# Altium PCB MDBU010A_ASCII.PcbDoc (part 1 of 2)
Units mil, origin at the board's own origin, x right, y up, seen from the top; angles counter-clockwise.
Board outline 3300 x 2500 mil, 2 copper layers (Top Layer, Bottom Layer), stack 64.8 mil thick; 105 components, 70 nets, 307 pads, 460 vias.
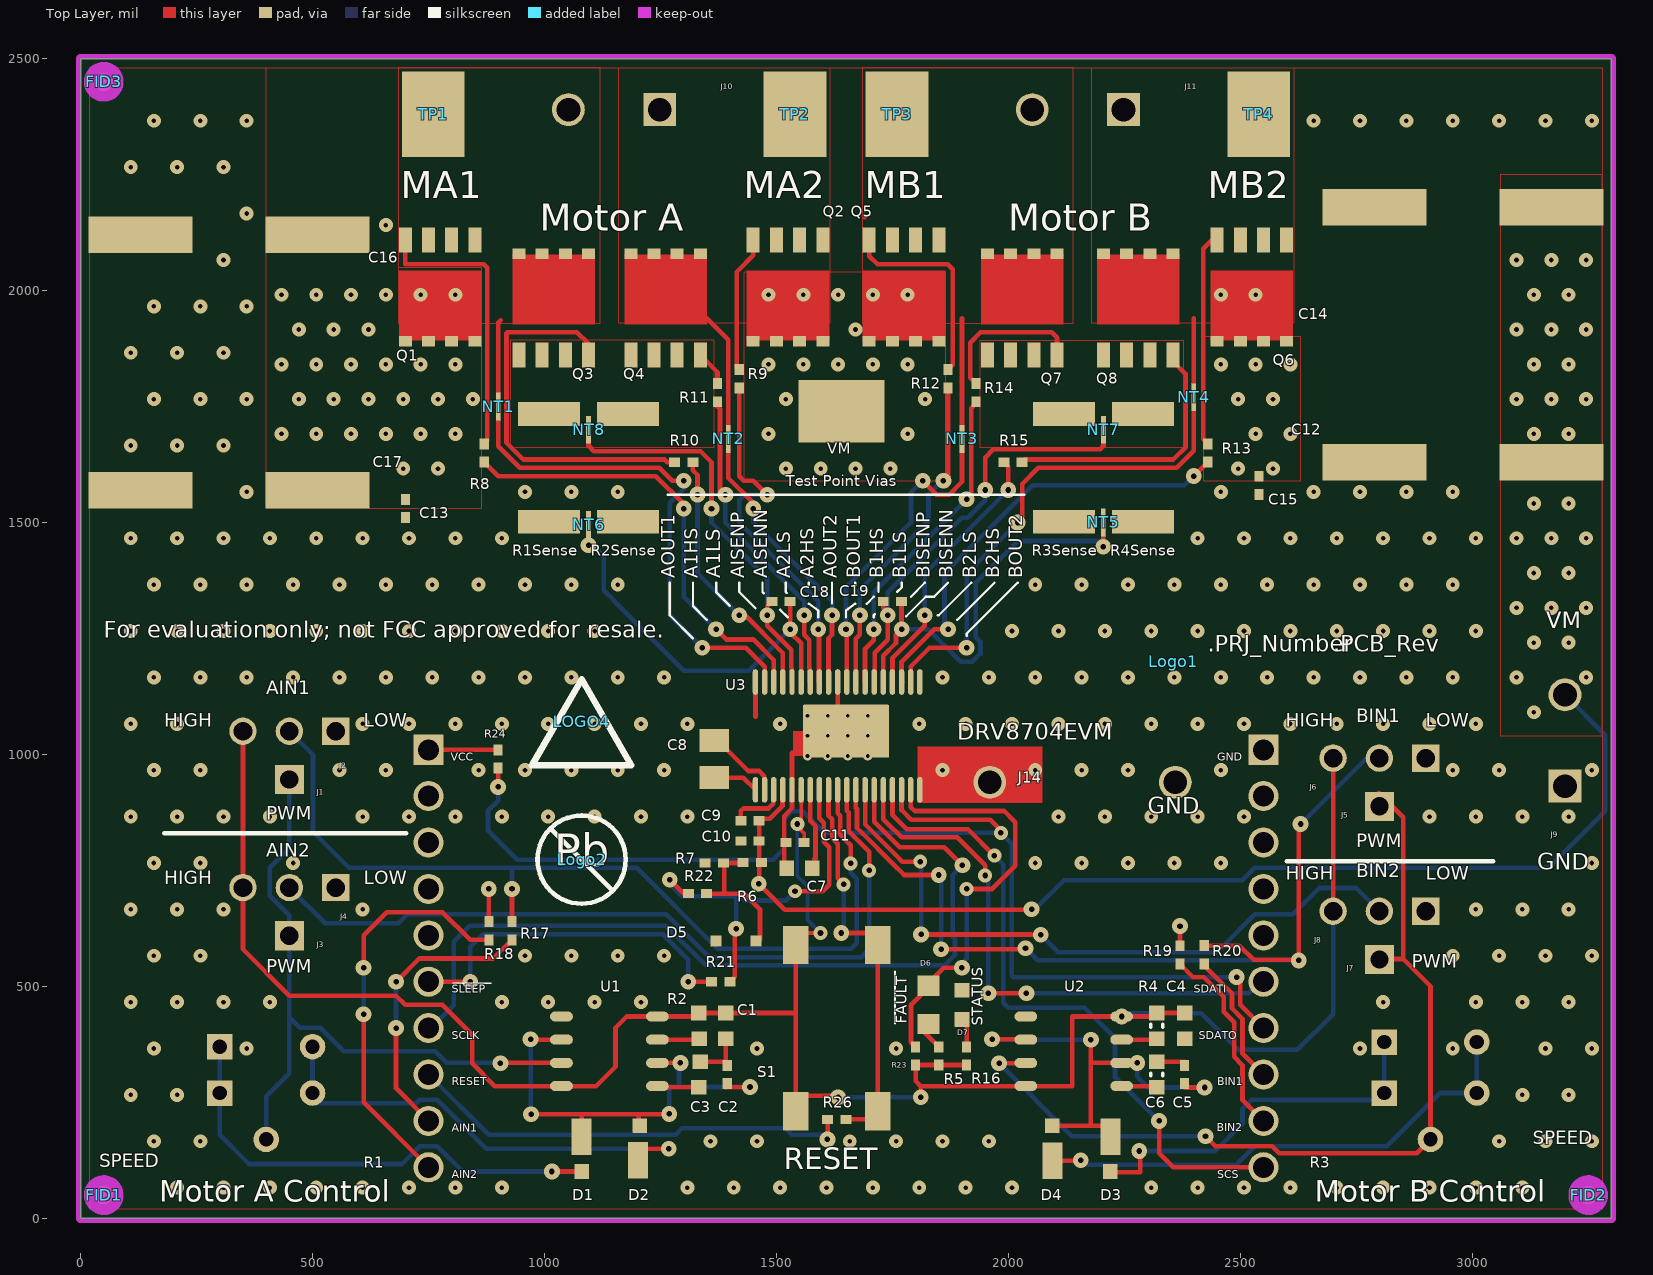
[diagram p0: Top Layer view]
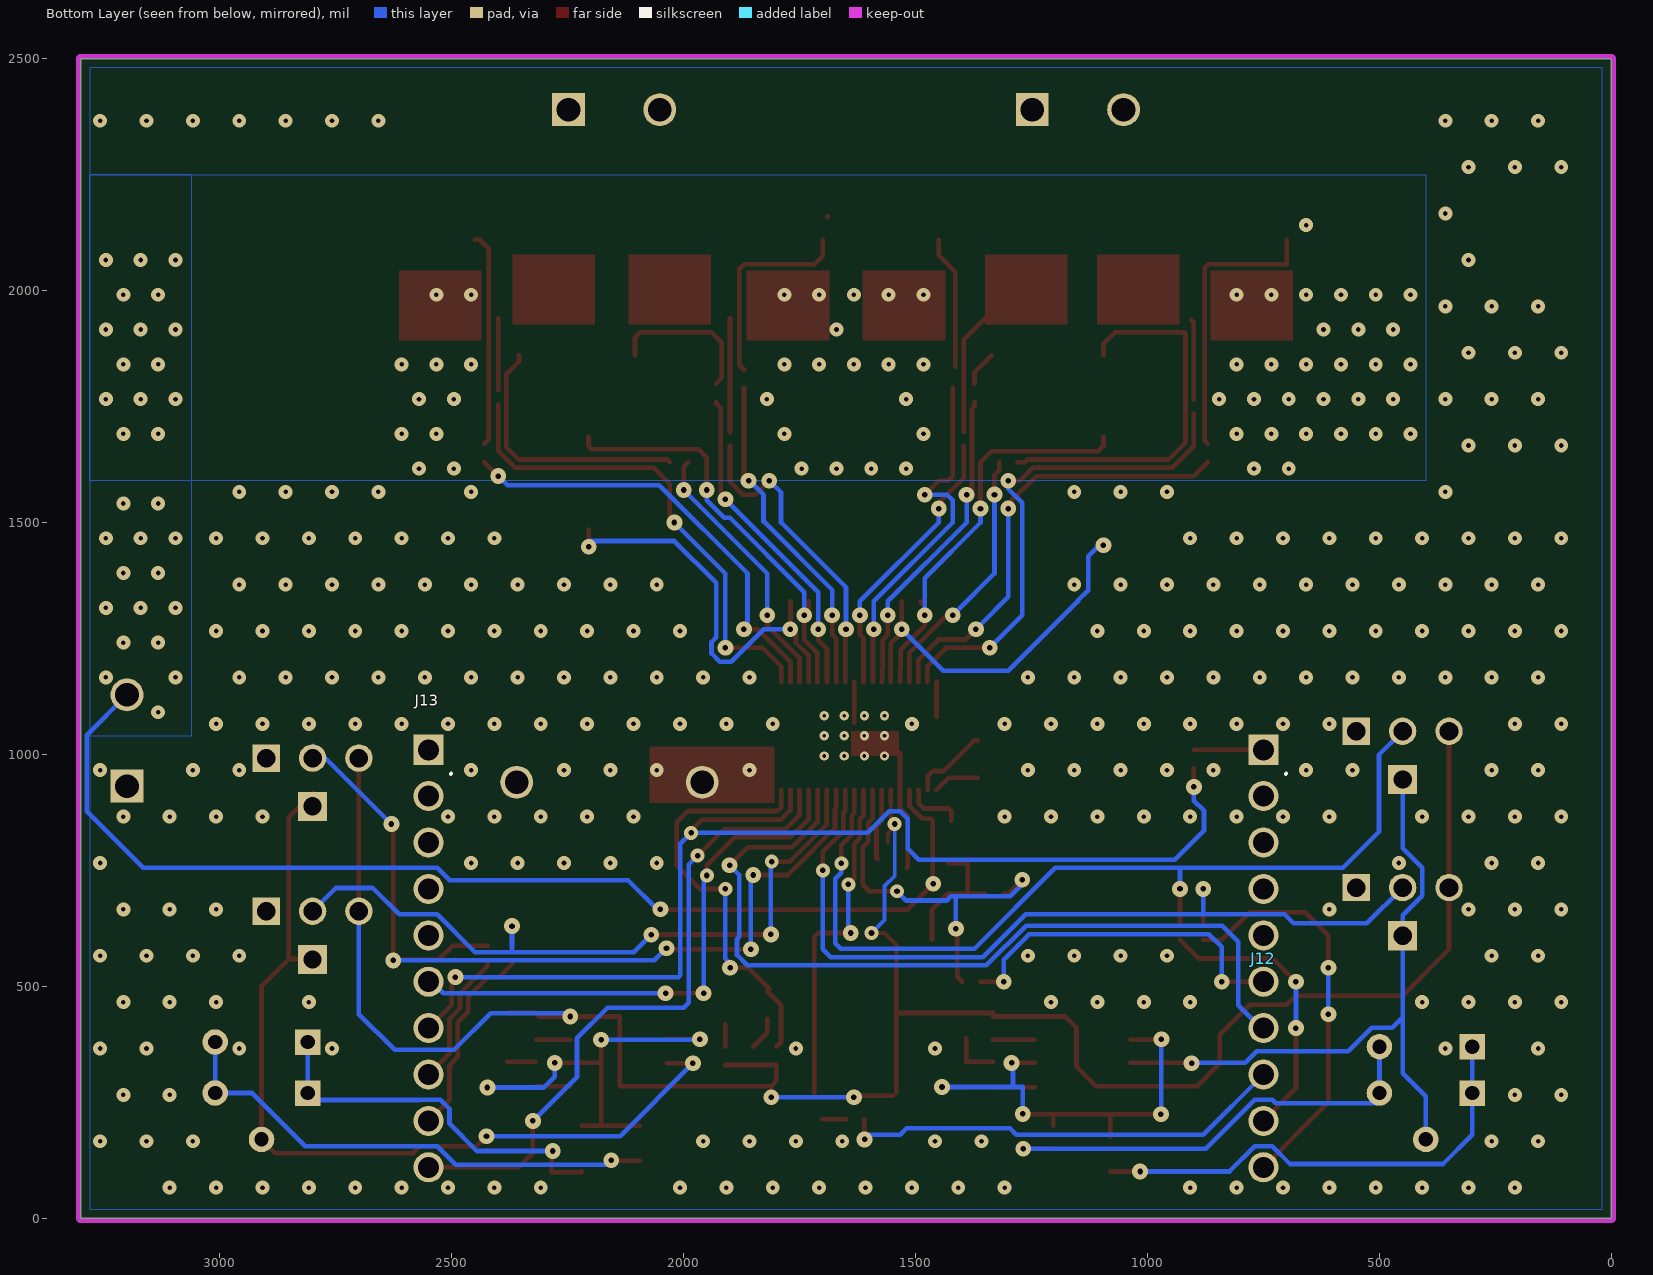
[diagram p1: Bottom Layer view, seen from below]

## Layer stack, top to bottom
Top Solder: solder mask 0.4, Solder Resist, Dk 3.5
Top Layer: signal copper 2.8
Dielectric1: core 59.2, FR-4, Dk 4.8
Bottom Layer: signal copper 2.8
Bottom Solder: solder mask 0.4, Solder Resist, Dk 3.5

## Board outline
0,0 3300,0 3300,2500 0,2500

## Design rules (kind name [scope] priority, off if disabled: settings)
AcuteAngle [All] p0: scope1count=1 scope1_0_kind=Board scope1_0_value=Board scope2count=1 scope2_0_kind=Board scope2_0_value=Board commentlength=0 minimum=4.50000000000000E+0001
AcuteAngle [All] p1: minimum=4.50000000000000E+0001 checktracksonly=FALSE
AssemblyTestPointUsage [All] p0: scope1count=1 scope1_0_kind=Board scope1_0_value=Board scope2count=1 scope2_0_kind=Board scope2_0_value=Board commentlength=0
AssemblyTestPointUsage [All] p1: valid=2
AssemblyTestpoint [All] p0: scope1count=1 scope1_0_kind=Board scope1_0_value=Board scope2count=1 scope2_0_kind=Board scope2_0_value=Board commentlength=0
Clearance Clearance_2 [All] p0: scope1count=1 scope1_0_kind=Board scope1_0_value=Board scope2count=1 scope2_0_kind=Board scope2_0_value=Board commentlength=0 gap=10
Clearance Clearance_1 [All] p0: scope1count=1 scope1_0_kind=Board scope1_0_value=Board scope2count=1 scope2_0_kind=Board scope2_0_value=Board commentlength=0 gap=10
Clearance [All] p0: scope1count=1 scope1_0_kind=Board scope1_0_value=Board scope2count=1 scope2_0_kind=Board scope2_0_value=Board commentlength=0 gap=7.87
Clearance Clearance_Poly [All] p0 off: scope1count=1 scope1_0_kind=Board scope1_0_value=Board scope2count=1 scope2_0_kind=Board scope2_0_value=Board commentlength=48 gap=25 // Protel DXP Scope 1 Expression Was: InPolygon
Clearance Clearance_BoardEdge [All] p0 off: scope1count=1 scope1_0_kind=Board scope1_0_value=Board scope2count=1 scope2_0_kind=Board scope2_0_value=Board commentlength=48 gap=75 // Protel DXP Scope 2 Expression Was: IsKeepOut
Clearance Clearance_BoardEdge_Poly [All] p0 off: scope1count=1 scope1_0_kind=Board scope1_0_value=Board scope2count=1 scope2_0_kind=Board scope2_0_value=Board commentlength=48 gap=25 // Protel DXP Scope 2 Expression Was: IsKeepOut
Clearance Clearance_BoardEdge_MountingHoles [All] p0 off: scope1count=1 scope1_0_kind=Board scope1_0_value=Board scope2count=1 scope2_0_kind=Board scope2_0_value=Board commentlength=48 gap=40 // Protel DXP Scope 2 Expression Was: IsKeepOut
Clearance Clearance_Keepouts [All] p0 off: scope1count=1 scope1_0_kind=Board scope1_0_value=Board scope2count=1 scope2_0_kind=Board scope2_0_value=Board commentlength=99 gap=0 // Protel DXP Scope 2 Expression Was: ((IsTrack Or IsArc) And Not InPoly) And IsFree and IsKeepOut
Clearance [All] p1: gap=7.87 ignorepadtopadclearanceinfootprint=FALSE except(0: Arc-Hole Track-Hole SMDPad-Hole THPad-Hole Via-Hole Fill-Hole Poly-Hole Region-Hole Text-Hole)
Clearance Clearance_2 [All] p2: gap=10 ignorepadtopadclearanceinfootprint=FALSE except(0: Arc-Hole Track-Hole SMDPad-Hole THPad-Hole Via-Hole Fill-Hole Poly-Hole Region-Hole Text-Hole)
Clearance Clearance_1 [All] p3: gap=10 ignorepadtopadclearanceinfootprint=FALSE except(0: Arc-Hole Track-Hole SMDPad-Hole THPad-Hole Via-Hole Fill-Hole Poly-Hole Region-Hole Text-Hole)
Clearance Clearance_Keepouts [((IsTrack Or IsArc) And Not InPoly) And IsFree and IsKeepOut vs ((IsTrack Or IsArc) And Not InPoly) And IsFree and IsKeepOut] p4: gap=0 ignorepadtopadclearanceinfootprint=FALSE
Clearance Clearance_BoardEdge_MountingHoles [OnCopper and InComponentClass('Mounting Holes') vs IsKeepOut] p5: gap=40 ignorepadtopadclearanceinfootprint=FALSE except(0: Arc-Hole Track-Hole SMDPad-Hole THPad-Hole Via-Hole Fill-Hole Poly-Hole Region-Hole Text-Hole)
Clearance Clearance_BoardEdge_Poly [OnCopper and InPoly vs IsKeepOut] p6: gap=25 ignorepadtopadclearanceinfootprint=FALSE except(0: Arc-Hole Track-Hole SMDPad-Hole THPad-Hole Via-Hole Fill-Hole Poly-Hole Region-Hole Text-Hole)
Clearance Clearance_BoardEdge [OnCopper and Not InComponentClass('Logo') and not InComponentClass('FiducialMark') and not InRegion(1000,500,4000,800) and Not IsKeepout vs IsKeepOut] p7: gap=75 ignorepadtopadclearanceinfootprint=FALSE except(0: Arc-Hole Track-Hole SMDPad-Hole THPad-Hole Via-Hole Fill-Hole Poly-Hole Region-Hole Text-Hole)
Clearance Clearance_Poly [InPolygon] p8: gap=25 ignorepadtopadclearanceinfootprint=FALSE except(0: Arc-Hole Track-Hole SMDPad-Hole THPad-Hole Via-Hole Fill-Hole Poly-Hole Region-Hole Text-Hole)
ComponentClearance [All] p0: scope1count=1 scope1_0_kind=Board scope1_0_value=Board scope2count=1 scope2_0_kind=Board scope2_0_value=Board commentlength=0 gap=10 collisioncheckmode=3
ComponentClearance ComponentClearance_THtoTH [All] p0 off: scope1count=1 scope1_0_kind=Board scope1_0_value=Board scope2count=1 scope2_0_kind=Board scope2_0_value=Board commentlength=54 gap=1 collisioncheckmode=3 // Protel DXP Scope 2 Expression Was: IsThruComponent
ComponentClearance ComponentClearance_THtoSMT [All] p0 off: scope1count=1 scope1_0_kind=Board scope1_0_value=Board scope2count=1 scope2_0_kind=Board scope2_0_value=Board commentlength=53 gap=100 collisioncheckmode=3 // Protel DXP Scope 2 Expression Was: IsSMTComponent
ComponentClearance ComponentClearance_SmallPassives [All] p0 off: scope1count=1 scope1_0_kind=Board scope1_0_value=Board scope2count=1 scope2_0_kind=Board scope2_0_value=Board commentlength=508 gap=20 collisioncheckmode=3 // Protel DXP Scope 2 Expression Was: HasFootprint('0201*') or HasFootprint('0402*') or HasFootprint('0508') or HasFootprint('0603*') or HasFootprint('0612') or HasFootprint('0805*') or HasFootprint('0815*') or HasFootprint('0830*') or HasFootprint('1206*') or HasFootprint('1210*') or HasFootprint('1808*') or HasFootprint('1812*') or HasFootprint('1825*') or HasFootprint('2010*') or HasFootprint('2220*') or HasFootprint('2225*') or HasFootprint('2512*') or HasFootprint('2728*') or HasFootprint('3518*')
ComponentClearance ComponentClearance_MountingHoles [All] p0: scope1count=1 scope1_0_kind=ComponentClass scope1_0_value="Mounting Holes" scope2count=1 scope2_0_kind=Board scope2_0_value=Board commentlength=0 gap=250 collisioncheckmode=3
ComponentClearance ComponentClearance_ScrewToNut [All] p0 off: scope1count=1 scope1_0_kind=Board scope1_0_value=Board scope2count=1 scope2_0_kind=Board scope2_0_value=Board commentlength=71 gap=5 collisioncheckmode=3 // Protel DXP Scope 2 Expression Was: (HasFootprint('Keystone_1902C'))
ComponentClearance ComponentClearance_Logo [All] p0: scope1count=1 scope1_0_kind=ComponentClass scope1_0_value=Logo scope2count=1 scope2_0_kind=Board scope2_0_value=Board commentlength=0 gap=50 collisioncheckmode=3
ComponentClearance ComponentClearance_Shunt [All] p0: scope1count=1 scope1_0_kind=ComponentClass scope1_0_value=Header scope2count=1 scope2_0_kind=ComponentClass scope2_0_value=Shunt commentlength=0 gap=0 collisioncheckmode=3
ComponentClearance ComponentClearance_MountingHoles_FiducialMarks [All] p0: scope1count=1 scope1_0_kind=ComponentClass scope1_0_value="Mounting Holes" scope2count=1 scope2_0_kind=ComponentClass scope2_0_value=FiducialMark commentlength=0 gap=50 collisioncheckmode=3
ComponentClearance ComponentClearance_MountingHoles_FiducialMarks [InComponentClass('Mounting Holes') vs InComponentClass('FiducialMark')] p1: gap=50 collisioncheckmode=3 verticalgap=10 showdistances=FALSE
ComponentClearance ComponentClearance_Shunt [InComponentClass('Header') vs InComponentClass('Shunt')] p2: gap=0 collisioncheckmode=3 verticalgap=0 showdistances=FALSE
ComponentClearance ComponentClearance_Logo [InComponentClass('Logo')] p3: gap=50 collisioncheckmode=3 verticalgap=10 showdistances=FALSE
ComponentClearance ComponentClearance_ScrewToNut [(HasFootprint('NY PMS 440 0025 PH')) vs (HasFootprint('Keystone_1902C'))] p4: gap=5 collisioncheckmode=3 verticalgap=10 showdistances=FALSE
ComponentClearance ComponentClearance_MountingHoles [InComponentClass('Mounting Holes')] p5: gap=250 collisioncheckmode=3 verticalgap=100000 showdistances=FALSE
ComponentClearance ComponentClearance_SmallPassives [HasFootprint('0201*') or HasFootprint('0402*') or HasFootprint('0508') or HasFootprint('0603*') or HasFootprint('0612') or HasFootprint('0805*') or HasFootprint('0815*') or HasFootprint('0830*') or HasFootprint('1206*') or HasFootprint('1210*') or HasFootprint('1808*') or HasFootprint('1812*') or HasFootprint('1825*') or HasFootprint('2010*') or HasFootprint('2220*') or HasFootprint('2225*') or HasFootprint('2512*') or HasFootprint('2728*') or HasFootprint('3518*') vs HasFootprint('0201*') or HasFootprint('0402*') or HasFootprint('0508') or HasFootprint('0603*') or HasFootprint('0612') or HasFootprint('0805*') or HasFootprint('0815*') or HasFootprint('0830*') or HasFootprint('1206*') or HasFootprint('1210*') or HasFootprint('1808*') or HasFootprint('1812*') or HasFootprint('1825*') or HasFootprint('2010*') or HasFootprint('2220*') or HasFootprint('2225*') or HasFootprint('2512*') or HasFootprint('2728*') or HasFootprint('3518*')] p6: gap=20 collisioncheckmode=3 verticalgap=10 showdistances=FALSE
ComponentClearance ComponentClearance_THtoSMT [IsThruComponent vs IsSMTComponent] p7: gap=100 collisioncheckmode=3 verticalgap=30 showdistances=FALSE
ComponentClearance ComponentClearance_THtoTH [IsThruComponent vs IsThruComponent] p8: gap=1 collisioncheckmode=3 verticalgap=0 showdistances=FALSE
ComponentClearance [All] p9: gap=10 collisioncheckmode=3 verticalgap=10 showdistances=FALSE
DiffPairsRouting [All] p0: scope1count=1 scope1_0_kind=Board scope1_0_value=Board scope2count=1 scope2_0_kind=Board scope2_0_value=Board commentlength=0
DiffPairsRouting [All] p1: maxlimit=100 minlimit=10 mostfreqgap=10 toplayer_minwidth=15 toplayer_maxwidth=15 toplayer_prefwidth=15 bottomlayer_minwidth=15 bottomlayer_maxwidth=15 bottomlayer_prefwidth=15 maxuncoupledlength=1000
FabricationTestPointUsage TestPointUsage [All] p0: scope1count=1 scope1_0_kind=Board scope1_0_value=Board scope2count=1 scope2_0_kind=Board scope2_0_value=Board commentlength=0 valid=2 allowmultiple=FALSE
FabricationTestPointUsage TestPointUsage [All] p1: valid=2 allowmultiple=FALSE
FabricationTestpoint Testpoint [All] p0: scope1count=1 scope1_0_kind=Board scope1_0_value=Board scope2count=1 scope2_0_kind=Board scope2_0_value=Board commentlength=0 side=3 testpointundercomponent=TRUE minsize=40 maxsize=100 preferedsize=60 minholesize=0 maxholesize=40 preferedholesize=32 testpointgrid=1
FabricationTestpoint Testpoint [All] p1: side=3 testpointundercomponent=TRUE minsize=40 maxsize=100 preferedsize=60 minholesize=0 maxholesize=40 preferedholesize=32 testpointgrid=1 allowsidetop=TRUE allowsidebottom=TRUE usegrid=TRUE gridtolerance=0.01
FanoutControl Fanout_Small [All] p0 off: scope1count=1 scope1_0_kind=Board scope1_0_value=Board scope2count=1 scope2_0_kind=Board scope2_0_value=Board commentlength=84 // Protel DXP Scope 1 Expression Was: (CompPinCount < 5)   Fanout_Small (Default Rule)
FanoutControl Fanout_Default [All] p0: scope1count=1 scope1_0_kind=Board scope1_0_value=Board scope2count=1 scope2_0_kind=Board scope2_0_value=Board commentlength=30 // Fanout_Default (Default Rule)
FanoutControl Fanout_SOIC [All] p0 off: scope1count=1 scope1_0_kind=Board scope1_0_value=Board scope2count=1 scope2_0_kind=Board scope2_0_value=Board commentlength=71 // Protel DXP Scope 1 Expression Was: IsSOIC   Fanout_SOIC (Default Rule)
FanoutControl Fanout_BGA [All] p0 off: scope1count=1 scope1_0_kind=Board scope1_0_value=Board scope2count=1 scope2_0_kind=Board scope2_0_value=Board commentlength=69 // Protel DXP Scope 1 Expression Was: IsBGA   Fanout_BGA (Default Rule)
FanoutControl Fanout_LCC [All] p0 off: scope1count=1 scope1_0_kind=Board scope1_0_value=Board scope2count=1 scope2_0_kind=Board scope2_0_value=Board commentlength=69 // Protel DXP Scope 1 Expression Was: IsLCC   Fanout_LCC (Default Rule)
FanoutControl Fanout_LCC [IsLCC] p1: bgadir=Out bgaviamode=Centered fanoutstyle=Auto fanoutdirection=Alternating viagrid=1 // Fanout_LCC (Default Rule)
FanoutControl Fanout_BGA [IsBGA] p2: bgadir=Out bgaviamode=Centered fanoutstyle=Auto fanoutdirection=Alternating viagrid=1 // Fanout_BGA (Default Rule)
FanoutControl Fanout_Default [All] p4: bgadir=Out bgaviamode=Centered fanoutstyle=Auto fanoutdirection=Alternating viagrid=1 // Fanout_Default (Default Rule)
FanoutControl Fanout_Small [(CompPinCount < 5)] p5: bgadir=Out bgaviamode=Centered fanoutstyle=Auto fanoutdirection=OutThenIn viagrid=1 // Fanout_Small (Default Rule)
Height [All] p0: scope1count=1 scope1_0_kind=Board scope1_0_value=Board scope2count=1 scope2_0_kind=Board scope2_0_value=Board commentlength=0
HoleSize [All] p0: scope1count=1 scope1_0_kind=Board scope1_0_value=Board scope2count=1 scope2_0_kind=Board scope2_0_value=Board commentlength=0 absolutevalues=TRUE maxlimit=251 minlimit=7.87 maxpercent=80.000 minpercent=20.000
HoleSize [All] p1: absolutevalues=TRUE maxlimit=251 minlimit=7.87 maxpercent=80.000 minpercent=20.000
HoleToHoleClearance [All] p0: scope1count=1 scope1_0_kind=Board scope1_0_value=Board scope2count=1 scope2_0_kind=Board scope2_0_value=Board commentlength=0
LayerPairs [All] p0: scope1count=1 scope1_0_kind=Board scope1_0_value=Board scope2count=1 scope2_0_kind=Board scope2_0_value=Board commentlength=0 enforce=TRUE
MinimumAnnularRing [All] p0: scope1count=1 scope1_0_kind=Board scope1_0_value=Board scope2count=1 scope2_0_kind=Board scope2_0_value=Board commentlength=0 minimumring=9
MinimumAnnularRing MinimumAnnularRing_ThermalPadVias [All] p0 off: scope1count=1 scope1_0_kind=Board scope1_0_value=Board scope2count=1 scope2_0_kind=Board scope2_0_value=Board commentlength=63 minimumring=5.91 // Protel DXP Scope 1 Expression Was: IsVia and InAnyComponent
MinimumAnnularRing MinimumAnnularRing_ThermalPadVias [IsVia and InAnyComponent] p1: minimumring=5.91
MinimumAnnularRing [All] p2: minimumring=9
MinimumSolderMaskSliver [All] p0: scope1count=1 scope1_0_kind=Board scope1_0_value=Board scope2count=1 scope2_0_kind=Board scope2_0_value=Board commentlength=0
MinimumSolderMaskSliver MinimumSolderMaskSliver_Logo [All] p0: scope1count=1 scope1_0_kind=ComponentClass scope1_0_value=Logo scope2count=1 scope2_0_kind=ComponentClass scope2_0_value=Logo commentlength=0
MinimumSolderMaskSliver MinimumSolderMaskSliver_Logo [InComponentClass('Logo') vs InComponentClass('Logo')] p1: minsoldermaskwidth=0.7
MinimumSolderMaskSliver [All] p2: minsoldermaskwidth=3.94
NetAntennae [All] p0: scope1count=1 scope1_0_kind=Board scope1_0_value=Board scope2count=1 scope2_0_kind=Board scope2_0_value=Board commentlength=0
PasteMaskExpansion [All] p0: scope1count=1 scope1_0_kind=Board scope1_0_value=Board scope2count=1 scope2_0_kind=Board scope2_0_value=Board commentlength=0 expansion=0
PlaneClearance [All] p0: scope1count=1 scope1_0_kind=Board scope1_0_value=Board scope2count=1 scope2_0_kind=Board scope2_0_value=Board commentlength=0 clearance=20
PlaneConnect [All] p0: scope1count=1 scope1_0_kind=Board scope1_0_value=Board scope2count=1 scope2_0_kind=Board scope2_0_value=Board commentlength=0 planeconnectstyle=Relief reliefexpansion=10 reliefentries=4 reliefconductorwidth=10 reliefairgap=10
PlaneConnect [All] p1: planeconnectstyle=Relief reliefexpansion=10 reliefentries=4 reliefconductorwidth=10 reliefairgap=10
PolygonConnect [All] p0: scope1count=1 scope1_0_kind=Board scope1_0_value=Board scope2count=1 scope2_0_kind=Board scope2_0_value=Board commentlength=0 connectstyle=Direct reliefconductorwidth=10 reliefentries=4 polygonreliefangle="90 Angle"
PolygonConnect [All] p1: connectstyle=Direct reliefconductorwidth=10 reliefentries=4 polygonreliefangle="90 Angle" airgapwidth=10
RoutingCorners [All] p0: scope1count=1 scope1_0_kind=Board scope1_0_value=Board scope2count=1 scope2_0_kind=Board scope2_0_value=Board commentlength=0 cornerstyle=45-Degree minsetback=100 maxsetback=100
RoutingLayers [All] p0: scope1count=1 scope1_0_kind=Board scope1_0_value=Board scope2count=1 scope2_0_kind=Board scope2_0_value=Board commentlength=0 top layer=Automatic bottom layer=Automatic
RoutingPriority [All] p0: scope1count=1 scope1_0_kind=Board scope1_0_value=Board scope2count=1 scope2_0_kind=Board scope2_0_value=Board commentlength=0
RoutingTopology [All] p0: scope1count=1 scope1_0_kind=Board scope1_0_value=Board scope2count=1 scope2_0_kind=Board scope2_0_value=Board commentlength=0 topology=Shortest
RoutingVias [All] p0: scope1count=1 scope1_0_kind=Board scope1_0_value=Board scope2count=1 scope2_0_kind=Board scope2_0_value=Board commentlength=0 holewidth=16 width=34 viastyle="Through Hole" minholewidth=7.87 minwidth=26 maxholewidth=21 maxwidth=65
RoutingVias ThermalPadVias [All] p0 off: scope1count=1 scope1_0_kind=Board scope1_0_value=Board scope2count=1 scope2_0_kind=Board scope2_0_value=Board commentlength=63 holewidth=7.87 width=19.68 viastyle="Through Hole" minholewidth=7.87 minwidth=19.68 maxholewidth=12.99 maxwidth=23.62 // Protel DXP Scope 1 Expression Was: IsVia and InAnyComponent
RoutingVias ThermalPadVias [IsVia and InAnyComponent] p1: holewidth=7.87 width=19.68 viastyle="Through Hole" minholewidth=7.87 minwidth=19.68 maxholewidth=12.99 maxwidth=23.62
RoutingVias [All] p2: holewidth=16 width=34 viastyle="Through Hole" minholewidth=7.87 minwidth=26 maxholewidth=21 maxwidth=65
ShortCircuit [All] p0: scope1count=1 scope1_0_kind=Board scope1_0_value=Board scope2count=1 scope2_0_kind=Board scope2_0_value=Board commentlength=0 allowed=FALSE
SilkToBoardRegionClearance [All] p0: scope1count=1 scope1_0_kind=Board scope1_0_value=Board scope2count=1 scope2_0_kind=Board scope2_0_value=Board commentlength=0
SilkToSilkClearance [All] p0: scope1count=1 scope1_0_kind=Board scope1_0_value=Board scope2count=1 scope2_0_kind=Board scope2_0_value=Board commentlength=0
SilkToSilkClearance SilkToSilkClearance_Pb-FreeLogo [All] p0 off: scope1count=1 scope1_0_kind=Board scope1_0_value=Board scope2count=1 scope2_0_kind=Board scope2_0_value=Board commentlength=120 // Protel DXP Scope 2 Expression Was: (HasFootprint('Pb-Free_Overlay_Medium') OR HasFootprint('Pb-Free_Overlay_Small'))
SilkToSilkClearance SilkToSilkClearance_Pb-FreeLogo [(HasFootprint('Pb-Free_Overlay_Medium') OR HasFootprint('Pb-Free_Overlay_Small')) vs (HasFootprint('Pb-Free_Overlay_Medium') OR HasFootprint('Pb-Free_Overlay_Small'))] p1: silktosilkclearance=0
SilkToSilkClearance [All] p2: silktosilkclearance=4
SilkToSolderMaskClearance "Silk to Solder Mask Opening" [All] p0: scope1count=1 scope1_0_kind=Board scope1_0_value=Board scope2count=1 scope2_0_kind=Board scope2_0_value=Board commentlength=0
SilkToSolderMaskClearance SilkToComonentPadClearance [All] p0 off: scope1count=1 scope1_0_kind=Board scope1_0_value=Board scope2count=1 scope2_0_kind=Board scope2_0_value=Board commentlength=63 // Protel DXP Scope 1 Expression Was: IsPad and InAnycomponent
SilkToSolderMaskClearance SilkToComonentPadClearance [IsPad and InAnycomponent] p1: minsilkscreentomaskgap=5 clearancetoexposedcopper=TRUE
SilkToSolderMaskClearance "Silk to Solder Mask Opening" [All] p2: minsilkscreentomaskgap=4 clearancetoexposedcopper=FALSE
SolderMaskExpansion [All] p0: scope1count=1 scope1_0_kind=Board scope1_0_value=Board scope2count=1 scope2_0_kind=Board scope2_0_value=Board commentlength=0 expansion=1.97
SolderMaskExpansion [All] p1: expansion=1.97
UnRoutedNet [All] p0: scope1count=1 scope1_0_kind=Board scope1_0_value=Board scope2count=1 scope2_0_kind=Board scope2_0_value=Board commentlength=0
UnpouredPolygon [All] p0: scope1count=1 scope1_0_kind=Board scope1_0_value=Board scope2count=1 scope2_0_kind=Board scope2_0_value=Board commentlength=0
Width [All] p0: scope1count=1 scope1_0_kind=Board scope1_0_value=Board scope2count=1 scope2_0_kind=Board scope2_0_value=Board commentlength=0 maxlimit=100 minlimit=6 preferedwidth=10
Width [All] p1: maxlimit=100 minlimit=6 preferedwidth=10 checkconnectedcopper=TRUE
16 further rules are at their usual default settings.

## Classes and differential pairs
component class FiducialMark: FID1 FID2 FID3
component class Logo: Logo1
component class MDBU010A_Hardware: !PCB FID1 FID2 FID3 J14 Logo1 Logo2 Logo3 LOGO4 ZZ1 ZZ2 ZZ3 ZZ4
component class AssemblyNote: ZZ1 ZZ2 ZZ3 ZZ4
component class MDBU010A: 20 C1 C2 C3 C4 C5 C6 C7 C8 C9 C10 C11 C12 C13 C14 C15 C16 C17 C18 C19 D1 D2 D3 D4 D5 D6 D7 J1 J2 J3 J4 J5 J6 J7 J8 J9 J10 J11 J12 J13 NT1 NT2 NT3 NT4 NT5 NT6 NT7 NT8 Q1 Q2 Q3 Q4 Q5 Q6 Q7 Q8 R1 R1Sense R2 R2Sense R3 R3Sense R4 R4Sense R5 R6 R7 R8 R9 R10 R11 R12 R13 R14 R15 R16 R17 R18 R19 R20 R21 R22 R23 R24 R26 S1 TP1 TP2 TP3 TP4 U1 U2 U3 VM
component class Header: J2 J4 J6 J8

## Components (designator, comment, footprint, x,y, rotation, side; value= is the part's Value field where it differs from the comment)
C1 "C0603C104M4RACTU" 0603L#1 1391,415 r90 top
C2 "GCM155R71E103KA37D" 0402L 1394,310 r270 top
C3 "C0603X103K5RACTU" 0603L#2 1336,310 r270 top
C4 "C0603C104M4RACTU" 0603L#1 2380,415 r90 top
C5 "GCM155R71E103KA37D" 0402L 2380,310 r270 top
C6 "C0603X103K5RACTU" 0603L#1 2320,310 r270 top
C7 "EMK107B7105KA-T" 0603L#1 1550,755 r180 top
C8 "GRM21BR71H104KA01L" 0805_HV 1366,990 r270 top
C9 "EMK105BJ105KVHF" 0402L 1443,857 r0 top
C10 "C0402C103J5RACTU" 0402L 1443,813 r0 top
C11 "GRM155R61A104KA01D" 0402L 1540,810 r180 top
C12 "EEE-TK1J221AQ" SM_RADIAL_H13 2980,1630 r180 top
C13 "C1005X7R1H104K050BB" 0402L 700,1530 r270 top
C14 "EEE-TK1J221AQ" SM_RADIAL_H13 2980,2180 r180 top
C15 "C1005X7R1H104K050BB" 0402L 2540,1580 r270 top
C16 "EEE-TK1J221AQ" SM_RADIAL_H13 320,2120 r180 top
C17 "EEE-TK1J221AQ" SM_RADIAL_H13 320,1570 r180 top
C18 "C1005C0G1E102J" 0402L 1510,1330 r0 top
C19 "C1005C0G1E102J" 0402L 1750,1330 r0 top
D1 "MSS1P4-M3/89A" MicroSMP#1 1080,150 r270 top
D2 "MSS1P4-M3/89A" MicroSMP#2 1205,150 r90 top
D3 "MSS1P4-M3/89A" MicroSMP#1 2220,150 r270 top
D4 "MSS1P4-M3/89A" MicroSMP#1 2095,150 r90 top
D5 "CMDZ5L1 TR" sod-323 1413.16,597.59 r180 top
D6 "150080SS75000" WL-SMCW_RED_0805 1828,460 r270 top
D7 "150060VS75000" WL-SMCW_GREEN 1900,460 r270 top
FID1 "Fiducial" Fiducial10-20 50,50 r0 top
FID2 "Fiducial" Fiducial10-20 3250,50 r0 top
FID3 "Fiducial" Fiducial10-20 50,2450 r0 top
J1 "PEC01SAAN" Sullins_PEC01SAAN#1 450,946 r0 top
J2 "PEC03SAAN" CONN_PEC03SAAN 450,1050 r180 top
J3 "PEC01SAAN" Sullins_PEC01SAAN#2 450,609 r180 top
J4 "PEC03SAAN" CONN_PEC03SAAN 450,713 r180 top
J5 "PEC01SAAN" Sullins_PEC01SAAN#2 2800,888 r90 top
J6 "PEC03SAAN" CONN_PEC03SAAN 2800,991.98 r180 top
J7 "PEC01SAAN" Sullins_PEC01SAAN#2 2800,558 r90 top
J8 "PEC03SAAN" CONN_PEC03SAAN 2800,661.98 r180 top
J9 "691 101 710 002" Wurth_691101710002 3200,1030 r90 top
J10 "691 101 710 002" Wurth_691101710002 1150,2390 r180 top
J11 "691 101 710 002" Wurth_691101710002 2150,2390 r180 top
J12 "SSW-110-23-F-S" CONN_SSW-110-23-F-S 750,560 r90 bottom
J13 "SSW-110-23-F-S" CONN_SSW-110-23-F-S 2550,560 r90 bottom
J14 "D3082-05" Harwin_D3082-05 2160,940 r180 top
Logo1 "Texas Instruments" TI_Stacked_Overlay_Small 2355,1200 r0 top
Logo2 "Pb-Free Symbol" Pb-Free_Overlay_Medium 1080,773.23 r0 top
Logo3 "FCC disclaimer" FCC_disclaimer 6220,6840 r90 top
LOGO4 "CAUTION HOT SURFACE" IEC_HotSurface_Small 1080,1070 r0 top
NT1 "Net-Tie" Net-Tie_10milWide_30milLong#1 900,1750 r90 top net-tie
NT2 "Net-Tie" Net-Tie_10milWide_30milLong#2 1400,1680 r270 top net-tie
NT3 "Net-Tie" Net-Tie_10milWide_30milLong#1 1900,1680 r90 top net-tie
NT4 "Net-Tie" Net-Tie_10milWide_30milLong#1 2400,1770 r270 top net-tie
NT5 "Net-Tie" Net-Tie_10milWide_30milLong#3 2196.77,1500 r90 top net-tie
NT6 "Net-Tie" Net-Tie_10milWide_30milLong#4 1100,1490 r90 top net-tie
NT7 "Net-Tie" Net-Tie_10milWide_30milLong#5 2210,1700 r90 top net-tie
NT8 "Net-Tie" Net-Tie_10milWide_30milLong#6 1090,1700 r90 top net-tie
Q1 "CSD18540Q5B" TRANS_NexFET_Q5B 775,2000 r270 top
Q2 "CSD18540Q5B" TRANS_NexFET_Q5B 1525,2000 r270 top
Q3 "CSD18540Q5B" TRANS_NexFET_Q5B 1020,1970 r90 top
Q4 "CSD18540Q5B" TRANS_NexFET_Q5B 1261,1970 r90 top
Q5 "CSD18540Q5B" TRANS_NexFET_Q5B 1775,2000 r270 top
Q6 "CSD18540Q5B" TRANS_NexFET_Q5B 2525,2000 r270 top
Q7 "CSD18540Q5B" TRANS_NexFET_Q5B 2030,1970 r90 top
Q8 "CSD18540Q5B" TRANS_NexFET_Q5B 2280,1970 r90 top
R1 "3386P-1-502LF" BOURNS_3386P 400,280 r0 top
R1Sense "CSRN2512FK15L0" 2512 1010,1617.87 r90 top
R2 "ERJ-3EKF1002V" 0603L#3 1333.32,415 r90 top
R2Sense "CSRN2512FK15L0" 2512 1180,1617.87 r90 top
R3 "3386P-1-502LF" BOURNS_3386P 2910,280 r0 top
R3Sense "CSRN2512FK15L0" 2512 2120,1617.87 r90 top
R4 "ERJ-3EKF1002V" 0603L#1 2320,415 r90 top
R4Sense "CSRN2512FK15L0" 2512 2290,1617.87 r90 top
R5 "CRCW0402200RFKED" 0402L 1850,350 r90 top
R6 "CRCW0402100KJNED" 0402L 1448,767 r0 top
R7 "CRCW0402100KJNED" 0402L 1366,766 r0 top
R8 "CRCW04020000Z0ED" 0402L 870,1650 r90 top
R9 "CRCW04020000Z0ED" 0402L 1420,1810 r270 top
R10 "CRCW04020000Z0ED" 0402L 1300,1630 r180 top
R11 "CRCW04020000Z0ED" 0402L 1373,1780 r270 top
R12 "CRCW04020000Z0ED" 0402L 1870,1810 r90 top
R13 "CRCW04020000Z0ED" 0402L 2430,1650 r270 top
R14 "CRCW04020000Z0ED" 0402L 1930,1780 r90 top
R15 "CRCW04020000Z0ED" 0402L 2010,1630 r180 top
R16 "CRCW0402200RFKED" 0402L 1910,350 r270 top
R17 "CRCW04020000Z0ED" 0402L 930,620 r90 top
R18 "CRCW04020000Z0ED" 0402L 880,620 r90 top
R19 "CRCW04020000Z0ED" 0402L 2370,567.81 r90 top
R20 "CRCW04020000Z0ED" 0402L 2422.28,568.17 r90 top
R21 "CRCW04020000Z0ED" 0402L 1380,510 r0 top
R22 "CRCW04020000Z0ED" 0402L 1330,700 r0 top
R23 "CRCW040210K0JNED" 0402L 1800,350 r270 top
R24 "CRCW04023K30JNED" 0402L 900,990 r90 top
R26 "CRCW04020000Z0ED" 0402L 1629.99,213.14 r0 top
S1 "4-1437565-1" SW_FSM4JSMA 1630,410 r180 top
TP1 "5016" Testpoint_Keystone_Compact 760,2380 r270 top
TP2 "5016" Testpoint_Keystone_Compact 1540,2380 r270 top
TP3 "5016" Testpoint_Keystone_Compact 1760,2380 r90 top
TP4 "5016" Testpoint_Keystone_Compact 2540,2380 r90 top
U1 "TLC555CD" D0008A_L 1140,360 r0 top
U2 "TLC555CD" D0008A_L 2141,360 r0 top
U3 "DRV8704DCPR" DCP0038A_N 1632,1040 r90 top
VM "5016" Testpoint_Keystone_Compact 1640,1740 r0 top (schematic designator TP5)
ZZ1 "Shorting plug J14 shall be raised to minimum height of 250mils above PCB" AssemblyNote 10,3330 r0 top
ZZ2 "These assemblies are ESD sensitive, ESD precautions shall be observed." AssemblyNote 10,3160 r0 top
ZZ3 "These assemblies must be clean and free from flux and all contaminants. Use of no clean flux is not acceptable." AssemblyNote 10,2980 r0 top
ZZ4 "These assemblies must comply with workmanship standards IPC-A-610 Class 2, unless otherwise specified." AssemblyNote 10,2810 r0 top

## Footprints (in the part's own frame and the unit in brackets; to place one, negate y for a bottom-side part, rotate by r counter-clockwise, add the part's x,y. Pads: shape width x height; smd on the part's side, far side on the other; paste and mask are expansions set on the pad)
0402L [mm] "0402 from SM-752 data"
  rect 0.6x0.5 smd: 1(-0.5,0) 2(0.5,0)
0603L#1 [mm] "0603 from SM-752 data"
  rect 0.8x0.85 smd: 1(-0.7,0) 2(0.7,0)
0603L#2 [mm] "0603 from SM-752 data"
  rect 0.8x0.85 smd: 1(-0.7,0) 2(0.7,-0.076)
0603L#3 [mm] "0603 from SM-752 data"
  rect 0.8x0.85 smd: 1(-0.7,0) 2(0.7,0.008)
0805_HV [mil] "0805 with 30mil clearance between pads"
  rect 50x63 smd: 1(-40,0) 2(40,0)
2512 [mm] "Chip Resistor, Body 6.3x3.2mm, IPC Medium Density"
  rect 1.3x3.4 smd: 1(-2.95,0) 2(2.95,0)
AssemblyNote [mil] "Assembly Note"
BOURNS_3386P [mil] "BOURND"
  rect 55x55 hole 31: 1(-100,-10)
  round 55 hole 31: 2(0,-110) 3(100,-10)
CONN_PEC03SAAN [mm] "SULLINS"
  rect 1.5x1.5 hole 1.016: 1(-2.54,0)
  round 1.5 hole 1.016: 2(0,0) 3(2.54,0)
CONN_SSW-110-23-F-S [mm] "SAMTEC"
  rect 1.65x1.65 hole 1.15: 1(11.43,0)
  round 1.65 hole 1.15: 2(8.89,0) 3(6.35,0) 4(3.81,0) 5(1.27,0) 6(-1.27,0) 7(-3.81,0) 8(-6.35,0) 9(-8.89,0) 10(-11.43,0)
  silkscreen extent 10.11,-1.24 10.13,-1.22
D0008A_L [mm] "SOIC, 8-Leads, Body 4.9x3.9mm, Pitch 1.27mm, IPC High Density"
  oval 1.25x0.55 smd: 1(-2.625,1.905) 2(-2.625,0.635) 3(-2.625,-0.635) 4(-2.625,-1.905) 5(2.625,-1.905) 6(2.625,-0.635) 7(2.625,0.635) 8(2.625,1.905)
DCP0038A_N [mm] "SOP, 38-Leads, Body 9.8x4.5mm, Pitch 0.5mm, Thermal Pad 4.7x2.9mm, IPC Medium Density"
  oval 1.4x0.3 smd: 1(-2.95,4.5) 2(-2.95,4) 3(-2.95,3.5) 4(-2.95,3) 5(-2.95,2.5) 6(-2.95,2) 7(-2.95,1.5) 8(-2.95,1) 9(-2.95,0.5) 10(-2.95,0) 11(-2.95,-0.5) 12(-2.95,-1) 13(-2.95,-1.5) 14(-2.95,-2) 15(-2.95,-2.5) 16(-2.95,-3) 17(-2.95,-3.5) 18(-2.95,-4) 19(-2.95,-4.5) 20(2.95,-4.5) 21(2.95,-4) 22(2.95,-3.5) 23(2.95,-3) 24(2.95,-2.5) 25(2.95,-2) 26(2.95,-1.5) 27(2.95,-1) 28(2.95,-0.5) 29(2.95,0) 30(2.95,0.5) 31(2.95,1) 32(2.95,1.5) 33(2.95,2) 34(2.95,2.5) 35(2.95,3) 36(2.95,3.5) 37(2.95,4) 38(2.95,4.5)
  rrect3% 2.9x4.7 smd: 39(0.254,-0.457)
FCC_disclaimer [mil]
Fiducial10-20 [mm]
  round 1 smd mask+0: 1(0,0)
  Top Layer keep-out circle w1.178: c0,0 r0.5
Harwin_D3082-05 [mm] "Shorting Plug, 10.16mm spacing, TH"
  round 1.8 hole 1.3: 1(-5.08,0) 2(5.08,0)
IEC_HotSurface_Small [mil]
  silkscreen extent -107,-93 107,92
MicroSMP#1 [mm] "SMD, 2-Leads, Body 2.2x1.3mm"
  rect 2x1.1 smd: 1(-0.65,0)
  rect 0.8x0.8 smd: 2(1.25,0)
MicroSMP#2 [mm] "SMD, 2-Leads, Body 2.2x1.3mm"
  rect 2x1.1 smd: 1(-0.635,0.084)
  rect 0.8x0.8 smd: 2(1.25,0)
Net-Tie_10milWide_30milLong#1 [mil] "10mil net tie, no solder mask opening, no solder paste"
  rect 30x10 smd paste-5 mask+0: 1(-15,0) 2(15,0)
Net-Tie_10milWide_30milLong#2 [mil] "10mil net tie, no solder mask opening, no solder paste"
  rect 30x10 smd paste-5 mask+0: 1(-15,-3.61) 2(15,-3.61)
Net-Tie_10milWide_30milLong#3 [mil] "10mil net tie, no solder mask opening, no solder paste"
  rect 30x10 smd paste-5 mask+0: 1(-15,-7.89) 2(15,-7.89)
Net-Tie_10milWide_30milLong#4 [mil] "10mil net tie, no solder mask opening, no solder paste"
  rect 30x10 smd paste-5 mask+0: 1(-10,5) 2(20,5)
Net-Tie_10milWide_30milLong#5 [mil] "10mil net tie, no solder mask opening, no solder paste"
  rect 30x10 smd paste-5 mask+0: 1(-15,5) 2(15,5)
Net-Tie_10milWide_30milLong#6 [mil] "10mil net tie, no solder mask opening, no solder paste"
  rect 30x10 smd paste-5 mask+0: 1(-15,-5) 2(15,-5)
Pb-Free_Overlay_Medium [mil]
  silkscreen extent -95,-95 95,95
SM_RADIAL_H13 [mm] "12.5 x 13.5mm:  Panasonic H13"
  rect 5.7x2 smd: 1(-4.85,0) 2(4.85,0)
sod-323 [mm] "NXP recommended land pattern"
  rect 0.6x0.6 smd paste-0.05: 1(-1.1,0) 2(1.1,0)
Sullins_PEC01SAAN#1 [mm] "SULLINS"
  rect 1.6x1.6 hole 1: 1(0,-0.005)
Sullins_PEC01SAAN#2 [mm] "SULLINS"
  rect 1.6x1.6 hole 1: 1(0,0)
SW_FSM4JSMA [mm] "Alcoswitch"
  rect 1.4x2.1 smd: 1(2.25,4.55) 2(2.25,-4.55) 3(-2.25,4.55) 4(-2.25,-4.55)
Testpoint_Keystone_Compact [mil] "Compact SMT test point"
  rect 185x135 smd: 1(0,0)
TI_Stacked_Overlay_Small [mil]
TRANS_NexFET_Q5B [mm] "TI recommended land pattern (nominal) November 2012"
  rect 1.372x0.71 smd paste-0.4: 1(-2.776,1.905) 2(-2.776,0.635) 3(-2.776,-0.635) 4(-2.776,-1.905)
  rect 0.59x0.71 smd paste-0.3: 5(2.776,-1.905) 6(2.776,-0.635) 7(2.776,0.635) 8(2.776,1.905)
  Top Layer region: -1.106,-2.26 2.744,-2.26 2.744,2.26 -1.106,2.26
WL-SMCW_GREEN [mm] "WURTH"
  rect 0.8x0.8 smd: 1(-0.8,0) 2(0.8,0)
WL-SMCW_RED_0805 [mm] "SMD, 2-Leads, Body 1.6x0.8mm"
  rect 1.1x1.2 smd: 1(-1.05,0) 2(1.05,0)
Wurth_691101710002 [mm] "Terminal Block, 5 mm, 2x1, TH"
  rect 1.8x1.8 hole 1.3: 1(-2.5,0)
  round 1.8 hole 1.3: 2(2.5,0)

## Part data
C1 C4: "CAP, CERM, 0.1 µF, 16 V, +/- 20%, X7R, 0603"
C2 C5: "CAP, CERM, 0.01 µF, 25 V, +/- 10%, X7R, 0402"
C3 C6: "CAP, CERM, 0.01 µF, 50 V, +/- 10%, X7R, 0603"
C7: "CAP, CERM, 1 µF, 16 V, +/- 10%, X7R, 0603"
C8: "CAP, CERM, 0.1 µF, 50 V, +/- 10%, X7R, 0805"
C9: "CAP, CERM, 1 µF, 16 V, +/- 10%, X5R, 0402"
C10: "CAP, CERM, 0.01 µF, 50 V, +/- 5%, X7R, 0402"
C11: "CAP, CERM, 0.1 µF, 10 V, +/- 10%, X5R, 0402"
C12 C14 C16 C17: "CAP, AL, 220 µF, 63 V, +/- 20%, 0.26 ohm, AEC-Q200 Grade 1, SMD"
C13 C15: "CAP, CERM, 0.1 µF, 50 V, +/- 10%, X7R, 0402"
C18 C19: "CAP, CERM, 1000 pF, 25 V, +/- 5%, C0G/NP0, 0402"
D1 D2 D3 D4: "Diode, Schottky, 40 V, 1 A, MicroSMP"
D5: "Diode, Zener, 5.1 V, 250 mW, SOD-323"
D6: "LED, Red, SMD"
D7: "LED, Green, SMD"
FID1 FID2 FID3: "Fiducial mark.  There is nothing to buy or mount."
J1 J3 J5 J7: "Header, 1x1, Tin, TH"
J2 J4 J6 J8: "Header, 100mil, 3x1, Tin, TH"
J9 J10 J11: "Terminal Block, 5 mm, 2x1, Tin, TH"
J12 J13: "Connector, Receptacle, 100mil, 10x1, Gold plated, TH"
J14: "1mm Uninsulated Shorting Plug, 10.16mm spacing, TH"
Logo1: library part TI_Logo, "Texas Instrument Corporate Signature"
Logo2: library part Pb-Free
Logo3: library part FCC_disclaimer, "FCC_disclaimer"
LOGO4: library part IEC_HotSurface, "IEC 61010-1 Hot Surface Warning"
NT1 NT2 NT3 NT4 NT5 NT6 NT7 NT8: "Single point connection between nets."
Q1 Q2 Q3 Q4 Q5 Q6 Q7 Q8: "MOSFET, N-CH, 60 V, 28 A, SON 5x6mm"
R1 R3: "TRIMMER, 5k ohm, 0.5W, TH"
R1Sense R2Sense R3Sense R4Sense: "RES, 0.015, 1%, 2 W, 2512"
R2 R4: "RES, 10.0 k, 1%, 0.1 W, 0603"
R5 R16: "RES, 200, 1%, 0.063 W, 0402"
R6 R7: "RES, 100 k, 5%, 0.063 W, 0402"
R8 R9 R10 R11 R12 R13 R14 R15 R17 R18 R19 R20 R21 R22 R26: "RES, 0, 5%, 0.063 W, 0402"
R23: "RES, 10 k, 5%, 0.063 W, 0402"
R24: "RES, 3.3 k, 5%, 0.063 W, 0402"
S1: "Switch, Tactile, SPST-NO, 0.05A, 12V, SMT"
TP1 TP2 TP3 TP4 VM: "Test Point, Compact, SMT"
U1 U2: "LinCMOS Timer, D0008A"
U3: "52-V Dual H-Bridge PWM Gate Driver, DCP0038A"
ZZ1 ZZ2 ZZ3 ZZ4: library part AssemblyNote

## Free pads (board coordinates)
  rect 55x55 hole 31: 0(300,370) 0(2810,380)
  round 55 hole 31: 1(500,370) 1(3010,380)

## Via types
v1: diameter 30, hole 10, Top Layer to Bottom Layer, tented both sides, 357 vias
v2: diameter 34, hole 12, Top Layer to Bottom Layer, 60 vias
v3: diameter 34, hole 12, Top Layer to Bottom Layer, tented top, 20 vias
v4: diameter 20, hole 8, Top Layer to Bottom Layer, 12 vias
v5: diameter 30, hole 12, Top Layer to Bottom Layer, 11 vias

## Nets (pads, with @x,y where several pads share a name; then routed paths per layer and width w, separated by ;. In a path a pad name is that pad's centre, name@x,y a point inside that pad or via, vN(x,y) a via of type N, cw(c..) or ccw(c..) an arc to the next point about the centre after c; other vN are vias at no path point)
\SLEEP: R21.2 R22.1 U3.8 | length 835.4
  Top Layer w10: v2(1270,730) 1300,700 R22.1@1310.32,700 ; R21.2@1399.69,510 1410,520.31 1410,621.01 v2(1413.15,624.16) ; v5(1540,705) 1600,705 1614.06,719.06 1614.06,800.02 1602.24,811.83 1602.24,852.58 1592.63,862.19 U3.8@1592.63,923.86
  Bottom Layer w10: v2(1270,730) 1270,720 1296.13,693.87 1423.98,693.87 1432.85,685 1520,685 v5(1540,705) ; v2(1413.15,624.16) 1413.15,690.72
A1HS: R8.1 U3.36 | length 951.4
  Top Layer w10: R8.1@870,1630.32 900.32,1600 1240,1600 1300,1540 v3(1300,1530) ; v2(1370,1270) 1392.13,1247.87 1449.88,1247.87 1494.2,1203.55 U3.36@1494.2,1156.14
  Bottom Layer w10: v3(1300,1530) 1300,1340 v2@1360,1280
A1LS: R10.1 U3.35 | length 535
  Top Layer w10: R10.1@1319.68,1630 1319.68,1612.56 1329.87,1602.37 v3(1329.87,1560.13) ; v2@1432.47,1300 1513.89,1218.58 U3.35@1513.89,1156.14
  Bottom Layer w10: v3(1329.87,1560.13) 1330,1560 1330,1390 v2@1410,1310
  other v2: 1420,1300
A2HS: R9.2 U3.31 | length 805.8
  Top Layer w10: R9.2@1420,1790.31 1420,1600 1430,1590 1450,1590 v3(1480,1560) ; v2@1581.51,1261.51 v2(1590,1270) 1591.72,1268.28 U3.31@1591.72,1157.05
  Bottom Layer w10: v3(1480,1560) 1432.25,1560 1420,1547.75 1420,1500 1590,1330 v2(1590,1270)
A2LS: R11.2 U3.32 | length 680.7
  Top Layer w10: R11.2@1373,1760.31 1373,1750.08 1378.51,1744.57 v3@1378.51,1561.49 ; v2(1560,1300) 1560.13,1299.87 1560.13,1257.63 1571.13,1246.62 1571.13,1186.48 1572.04,1185.57 1572.04,1157.05 U3.32@1572.94,1156.14
  Bottom Layer w10: v3(1390,1560) 1390,1500 1560,1330 v2(1560,1300)
AIN1: J2.2 R17.2 U3.10 | length 1982.9
  Top Layer w10: R17.2@930,639.69 v2(930,710) ; U3.10@1632,923.86 1632,873.38 1637.99,867.39 1637.99,826.64 1649.8,814.82 1660,804.61 v5(1660,765)
  Bottom Layer w10: J2.2@450,1050 501,999 501,833 578.6,755.4 584.86,755.4 584.91,755.35 930,755.35 ; v2(930,710) 930,755.35 ; v5(1660,765) 1660,745 1672.87,732.13 1672.87,592.87 1661,581 1373,581 1198.65,755.35 930,755.35
AIN2: J4.2 R18.2 U3.11 | length 1823.9
  Top Layer w10: R18.2@880,639.69 v2(880,710) ; U3.11@1651.68,923.86 1651.68,878.97 1655.87,874.79 1655.87,834.04 1667.68,822.23 ; 1667.68,822.21 1700,789.89 v5(1700,750)
  Bottom Layer w10: J4.2@450,713 527,636 685.29,636 704.65,655.35 880,655.35 ; v2(880,710) 880,655.35 ; v5(1700,750) 1700,580 1683.13,563.13 1354.87,563.13 1262.65,655.35 880,655.35
AISENN: C18.2 NT6.1 U3.33 | length 815.6
  Top Layer w10: C18.2@1529.69,1330 1529.87,1329.81 v2@1529.87,1270.13 ; v2(1530,1270) 1530,1262.47 1553.26,1239.21 U3.33@1553.26,1156.14
  Bottom Layer w10: v3@1095,1460 1128.13,1426.87 1128.13,1353.63 1150,1331.75 1150,1330 1300,1180 1440,1180 v2(1530,1270)
  other v3: 1095,1451.09
AISENP: C18.1 NT8.1 U3.34 | length 878.2
  Top Layer w10: NT8.1@1095,1685 1095,1665 1106.38,1653.62 1336.38,1653.62 1360,1630 v3(1360,1530) ; C18.1@1490.32,1330 1480,1319.68 v2(1480,1300) 1480,1277.75 1531.76,1225.99 1531.76,1186.48 1532.67,1185.57 U3.34@1532.67,1157.05
  Bottom Layer w10: v3(1360,1530) 1360,1500 1480,1380 v2(1480,1300)
AOUT1: NT1.1 U3.37 | length 1072.8
  Top Layer w10: NT1.1@900,1735 900.28,1734.72 900.28,1664.45 946.85,1617.87 1247.4,1617.87 1275.28,1590 v3(1300,1590) ; v2(1340,1230) 1433.54,1230 1474.52,1189.02 U3.37@1474.52,1156.14
  Bottom Layer w10: v3(1300,1590) 1300,1572.25 1270.13,1542.37 1270.13,1299.87 v2@1330,1240
AOUT2: NT2.2 U3.30 | length 594.5
  Top Layer w10: NT2.2@1396.39,1665 1396.39,1595.86 1450,1542.25 v3@1450,1540 ; U3.30@1612.31,1156.14 1612.31,1250.07 1619.87,1257.63 v2@1619.87,1299.87
  Bottom Layer w10: v3(1450,1530) 1450,1500 1620,1330 v2(1620,1300)
B1HS: R12.1 U3.27 | length 717.7
  Top Layer w10: U3.27@1671.37,1156.14 1671.37,1249.12 1679.87,1257.63 v2@1679.87,1299.87 ; v3(1860,1590) 1870,1600 R12.1@1870,1790.32
  Bottom Layer w10: v2(1680,1300) 1680,1354.53 1827.74,1502.26 1827.74,1560.13 1857.61,1590 v3(1860,1590)
B1LS: R14.1 U3.26 | length 679
  Top Layer w10: U3.26@1691.06,1156.14 1691.06,1227.44 1710,1246.39 v2@1710,1260 ; v3@1920,1560 1920,1746.69 1930,1756.69 R14.1@1930,1760.32
  Bottom Layer w10: v2(1710,1270) 1710,1350 v3(1910,1550)
B2HS: R13.2 U3.22 | length 964.3
  Top Layer w10: U3.22@1770.7,1156.14 U3.22@1769.8,1156.14 1769.8,1199.8 1840,1270 v2(1870,1270) ; v2(2399.69,1600) R13.2@2430,1630.31
  Bottom Layer w10: v2(1870,1270) 1862.25,1277.75 1862.25,1390 2052.25,1580 2379.69,1580 v2(2399.69,1600)
B2LS: R15.2 U3.23 | length 592.3
  Top Layer w10: U3.23@1751.02,1156.14 U3.23@1750.11,1156.14 1750.11,1207.31 1820,1277.2 v2(1820,1300) ; R15.2@1990.31,1630 2000,1620.31 v3(2000,1570)
  Bottom Layer w10: v2(1820,1300) 1820,1390 v3(2000,1570) v3@2000,1560
BIN1: J6.2 R20.2 U3.12 | length 1980.9
  Top Layer w10: U3.12@1672.28,922.95 U3.12@1671.37,923.86 1671.37,884.56 1673.74,882.19 1673.74,841.44 1685.55,829.63 ; 1685.55,829.62 1750.92,764.25 ; 1750.93,764.25 1775.18,740 v2@1840,740 ; v2(1855,580) 2028,580 2030,582 v2(2037,582) ; R20.2@2422.28,587.86 2498.14,587.86 2529,557 v2@2625,557 ; v2(2626,556) v2@2626,846
  Bottom Layer w10: v2(1850,740) 1855,735 v2(1855,580) ; v2(2037,582) 2063,556 v2(2626,556) ; v2(2630,850) J6.2@2798.16,1018.16
BIN2: J8.2 R19.2 U3.13 | length 1566.3
  Top Layer w10: U3.13@1691.06,923.86 1691.61,923.3 1691.61,848.85 1703.43,837.04 ; 1703.43,837.02 1758.32,782.13 ; 1758.33,782.13 1771.46,769 v5(1810,769) ; v2@1811,611 v2(1811.87,611.87) 2049.37,611.87 2050.25,611 v2(2070,611) ; R19.2@2370,587.5 v2(2370,630)
  Bottom Layer w10: v5(1810,769) 1811.87,767.13 v2(1811.87,611.87) ; v2(2070,611) 2107.13,573.87 2370,573.87 ; v2(2370,630) 2370,573.87 ; J8.2@2800.05,661.98 2750.05,711.98 2670,711.98 2613.37,655.35 2531.21,655.35 2449.73,573.87 2370,573.87
BISENN: C19.2 NT5.1 U3.24 | length 894.3
  Top Layer w10: U3.24@1730.43,1156.14 1730.43,1212.9 1757.75,1240.22 1757.75,1257.75 v2(1770,1270) ; C19.2@1769.69,1330 1769.75,1329.94 v2@1769.75,1270.25 ; v3@2204.66,1450.53 NT5.1@2204.66,1485
  Bottom Layer w10: v2(1770,1270) 1827.75,1270 1897.63,1200.13 1922.37,1200.13 1939.87,1217.63 1939.87,1242.37 1930,1252.25 1930,1370 2020,1460 v3@2200,1460
  other v3: 2204.66,1447.93
BISENP: C19.1 NT7.1 U3.25 | length 920
  Top Layer w10: U3.25@1710.74,1156.14 1711.65,1156.14 1711.65,1219.4 1739.87,1247.63 v2(1739.87,1300) 1739.87,1306.66 1730.32,1316.22 C19.1@1730.32,1330 ; v3@1940,1570 v3(1950,1570) 1950,1640 1967.68,1657.68 2197.68,1657.68 2205,1665 NT7.1@2205,1685
  Bottom Layer w10: v2(1739.87,1300) 1739.87,1349.87 1900,1510 1912.25,1510 1950,1547.75 v3(1950,1570)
